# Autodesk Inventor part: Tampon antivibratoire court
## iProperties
Shininess: 64.0
Length Units: 11269
Angle Units: 11279
Time Units: 11290
Mass Units: 11283
Length Display Precision: 3
Angle Display Precision: 2
Compacted: True
Part Number: Tampon antivibratoire court
Document SubType Name: Modeling
Created: 2005-01
Material: Par défaut
Designer: lolo (Laurent Moretti)
Density: 0.0
Volumn: 0.0
Area: 0.0
PropertySet Name: Model Information
Control State: 0
Master: False
Checked Out: False
Author: lolo (Laurent Moretti)
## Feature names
1. Base1
